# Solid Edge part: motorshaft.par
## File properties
Author: Robert a Rhodes jr
Template: NORMENG.PAR
Last saved by: TIET
Revision: 5
Application: Solid Edge
Accuracy: 0.99
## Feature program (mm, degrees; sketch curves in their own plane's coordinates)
sketch for "unnamed Protrusion 1" plane through (0, 0, 0) normal (0, -1, 0) x-axis (1, 0, 0)
  circle centre (0, 0) radius 18.415
extrude "unnamed Protrusion 1" add finite 609.6 along -normal
sketch for "unnamed RevolvedCutout 1" plane through (0, 0, 0) normal (0, 0, 1) x-axis (1, 0, 0)
  line (18.415, 592.328) -> (18.415, 596.9)
  line (18.415, 596.9) -> (14.1403, 596.9)
  line (14.1403, 596.9) -> (14.1403, 592.328)
  line (14.1403, 592.328) -> (18.415, 592.328)
revolve "unnamed RevolvedCutout 1" cut finite 360 deg about sketch line (-1.0997, 601.5888) -> (-1.0997, 629.75)
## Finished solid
Body 1: solid body, 7 faces, 6 edges, 0 vertices.
  Faces by surface: plane 4, cylinder 3
  Edges by curve: circle 6
Bounding box of the edges (mm): 36.830 x 609.600 x 36.830, from (-18.415, 0, -18.415) to (18.415, 609.6, 18.415).
Cylindrical faces by radius (mm): R15.24 x1, R18.415 x2
Planar faces by outward normal: +y 2, -y 2
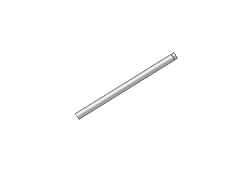
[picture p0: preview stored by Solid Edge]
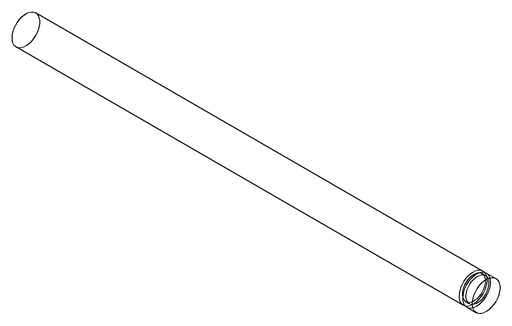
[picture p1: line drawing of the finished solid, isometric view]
